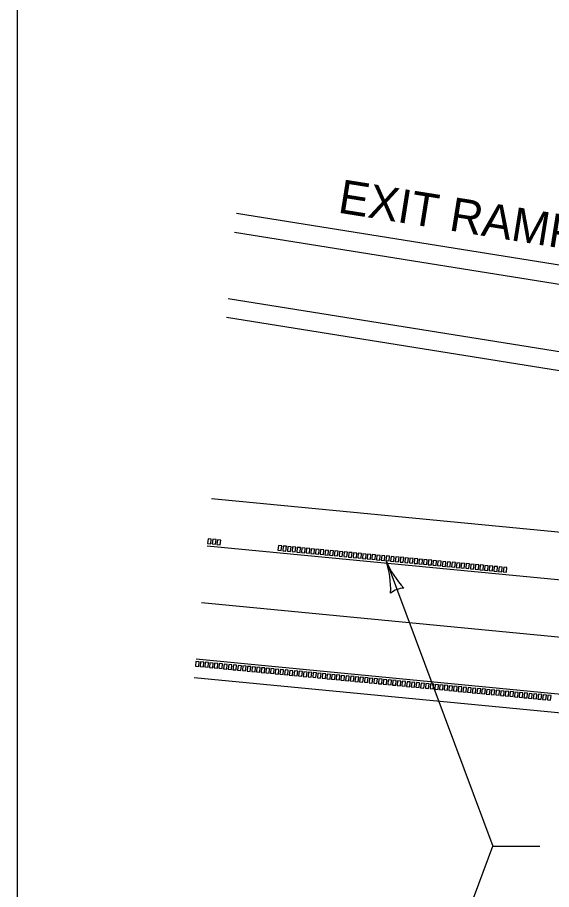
# Model space of a CAD drawing. Extents: x 49991.4 to 50021, y 49987.6 to 50011.4.
# Drawn here: x 49999.384 to 50000.652, y 49990.3 to 49992.373 of the extents above; entities that cross this region are included whole.
import ezdxf

# ---------------------------------------------------------------- set-up
doc = ezdxf.new("R2010")
doc.units = 0
for name, color, linetype in [('Level 1', 7, 'Continuous'), ('Level 2', 7, 'Continuous'), ('Level 3', 7, 'Continuous')]:
    doc.layers.add(name, color=color, linetype=linetype)

msp = doc.modelspace()

# ---------------------------------------------------------------- linework, layer by layer
at = {"layer": 'Level 1'}
for p, q in [((50003.1457, 49991.3876), (49999.9039, 49991.9068)), ((49999.8995, 49991.862), (50003.1403, 49991.3428)), ((49999.8843, 49991.7048), (50003.1155, 49991.1873)), ((50000.9907, 49991.1182), (49999.8446, 49991.2286)), ((49999.8339, 49991.1166), (50000.9799, 49991.0062)), ((49999.8209, 49990.9822), (50000.967, 49990.8718)), ((49999.8079, 49990.8478), (50000.9541, 49990.7374)), ((50000.9497, 49990.6926), (49999.8035, 49990.803))]:
    msp.add_line(p, q, dxfattribs=at)
for points in [[(49999.3835, 49998.9992), (50016.7501, 49998.9992), (50016.7501, 49987.7988), (49999.3835, 49987.7988)], [(49999.8353, 49991.1223), (49999.8431, 49991.1215), (49999.8441, 49991.1327), (49999.8364, 49991.1334)], [(49999.8465, 49991.1212), (49999.8542, 49991.1205), (49999.8553, 49991.1316), (49999.8475, 49991.1324)], [(49999.8576, 49991.1201), (49999.8654, 49991.1194), (49999.8664, 49991.1305), (49999.8587, 49991.1313)], [(50000.0025, 49991.1062), (50000.0103, 49991.1054), (50000.0114, 49991.1166), (50000.0036, 49991.1173)], [(50000.0137, 49991.1051), (50000.0214, 49991.1043), (50000.0225, 49991.1155), (50000.0148, 49991.1162)], [(50000.0248, 49991.104), (50000.0326, 49991.1033), (50000.0337, 49991.1144), (50000.0259, 49991.1152)], [(50000.036, 49991.1029), (50000.0437, 49991.1022), (50000.0448, 49991.1133), (50000.037, 49991.1141)], [(50000.0471, 49991.1019), (50000.0549, 49991.1011), (50000.056, 49991.1123), (50000.0482, 49991.113)], [(50000.0583, 49991.1008), (50000.066, 49991.1001), (50000.0671, 49991.1112), (50000.0593, 49991.1119)], [(50000.0694, 49991.0997), (50000.0772, 49991.099), (50000.0783, 49991.1101), (50000.0705, 49991.1109)], [(50000.0806, 49991.0987), (50000.0883, 49991.0979), (50000.0894, 49991.1091), (50000.0816, 49991.1098)], [(50000.0917, 49991.0976), (50000.0995, 49991.0968), (50000.1006, 49991.108), (50000.0928, 49991.1087)], [(50000.1029, 49991.0965), (50000.1106, 49991.0958), (50000.1117, 49991.1069), (50000.1039, 49991.1077)], [(50000.114, 49991.0954), (50000.1218, 49991.0947), (50000.1229, 49991.1058), (50000.1151, 49991.1066)], [(50000.1252, 49991.0944), (50000.1329, 49991.0936), (50000.134, 49991.1048), (50000.1262, 49991.1055)], [(50000.1363, 49991.0933), (50000.1441, 49991.0925), (50000.1451, 49991.1037), (50000.1374, 49991.1044)], [(50000.1475, 49991.0922), (50000.1552, 49991.0915), (50000.1563, 49991.1026), (50000.1485, 49991.1034)], [(50000.1586, 49991.0911), (50000.1664, 49991.0904), (50000.1674, 49991.1015), (50000.1597, 49991.1023)], [(50000.1698, 49991.0901), (50000.1775, 49991.0893), (50000.1786, 49991.1005), (50000.1708, 49991.1012)], [(50000.1809, 49991.089), (50000.1887, 49991.0882), (50000.1897, 49991.0994), (50000.182, 49991.1001)], [(50000.1921, 49991.0879), (50000.1998, 49991.0872), (50000.2009, 49991.0983), (50000.1931, 49991.0991)], [(50000.2032, 49991.0868), (50000.211, 49991.0861), (50000.212, 49991.0972), (50000.2043, 49991.098)], [(50000.2143, 49991.0858), (50000.2221, 49991.085), (50000.2232, 49991.0962), (50000.2154, 49991.0969)], [(50000.2255, 49991.0847), (50000.2333, 49991.0839), (50000.2343, 49991.0951), (50000.2266, 49991.0958)], [(50000.2366, 49991.0836), (50000.2444, 49991.0829), (50000.2455, 49991.094), (50000.2377, 49991.0948)], [(50000.2478, 49991.0825), (50000.2556, 49991.0818), (50000.2566, 49991.0929), (50000.2489, 49991.0937)], [(50000.2589, 49991.0815), (50000.2667, 49991.0807), (50000.2678, 49991.0919), (50000.26, 49991.0926)], [(50000.2701, 49991.0804), (50000.2779, 49991.0796), (50000.2789, 49991.0908), (50000.2712, 49991.0915)], [(50000.2812, 49991.0793), (50000.289, 49991.0786), (50000.2901, 49991.0897), (50000.2823, 49991.0905)], [(50000.2924, 49991.0782), (50000.3002, 49991.0775), (50000.3012, 49991.0886), (50000.2935, 49991.0894)], [(50000.3035, 49991.0772), (50000.3113, 49991.0764), (50000.3124, 49991.0876), (50000.3046, 49991.0883)], [(50000.3147, 49991.0761), (50000.3224, 49991.0754), (50000.3235, 49991.0865), (50000.3158, 49991.0872)], [(50000.3258, 49991.075), (50000.3336, 49991.0743), (50000.3347, 49991.0854), (50000.3269, 49991.0862)], [(50000.337, 49991.074), (50000.3447, 49991.0732), (50000.3458, 49991.0844), (50000.3381, 49991.0851)], [(50000.3481, 49991.0729), (50000.3559, 49991.0721), (50000.357, 49991.0833), (50000.3492, 49991.084)], [(50000.3593, 49991.0718), (50000.367, 49991.0711), (50000.3681, 49991.0822), (50000.3604, 49991.083)], [(50000.3704, 49991.0707), (50000.3782, 49991.07), (50000.3793, 49991.0811), (50000.3715, 49991.0819)], [(50000.3816, 49991.0697), (50000.3893, 49991.0689), (50000.3904, 49991.0801), (50000.3826, 49991.0808)], [(50000.3927, 49991.0686), (50000.4005, 49991.0678), (50000.4016, 49991.079), (50000.3938, 49991.0797)], [(50000.4039, 49991.0675), (50000.4116, 49991.0668), (50000.4127, 49991.0779), (50000.4049, 49991.0787)], [(50000.415, 49991.0664), (50000.4228, 49991.0657), (50000.4239, 49991.0768), (50000.4161, 49991.0776)], [(50000.4262, 49991.0654), (50000.4339, 49991.0646), (50000.435, 49991.0758), (50000.4272, 49991.0765)], [(50000.4373, 49991.0643), (50000.4451, 49991.0635), (50000.4462, 49991.0747), (50000.4384, 49991.0754)], [(50000.4485, 49991.0632), (50000.4562, 49991.0625), (50000.4573, 49991.0736), (50000.4495, 49991.0744)], [(50000.4596, 49991.0621), (50000.4674, 49991.0614), (50000.4685, 49991.0725), (50000.4607, 49991.0733)], [(50000.4708, 49991.0611), (50000.4785, 49991.0603), (50000.4796, 49991.0715), (50000.4718, 49991.0722)], [(50000.4819, 49991.06), (50000.4897, 49991.0592), (50000.4907, 49991.0704), (50000.483, 49991.0711)], [(50000.4931, 49991.0589), (50000.5008, 49991.0582), (50000.5019, 49991.0693), (50000.4941, 49991.0701)], [(50000.5042, 49991.0578), (50000.512, 49991.0571), (50000.513, 49991.0682), (50000.5053, 49991.069)], [(50000.5154, 49991.0568), (50000.5231, 49991.056), (50000.5242, 49991.0672), (50000.5164, 49991.0679)], [(50000.5265, 49991.0557), (50000.5343, 49991.0549), (50000.5353, 49991.0661), (50000.5276, 49991.0668)], [(50000.5377, 49991.0546), (50000.5454, 49991.0539), (50000.5465, 49991.065), (50000.5387, 49991.0658)], [(49999.8063, 49990.8309), (49999.8141, 49990.8302), (49999.8152, 49990.8413), (49999.8074, 49990.8421)], [(49999.8175, 49990.8298), (49999.8252, 49990.8291), (49999.8263, 49990.8402), (49999.8185, 49990.841)], [(49999.8286, 49990.8288), (49999.8364, 49990.828), (49999.8375, 49990.8392), (49999.8297, 49990.8399)], [(49999.8398, 49990.8277), (49999.8475, 49990.8269), (49999.8486, 49990.8381), (49999.8408, 49990.8388)], [(49999.8509, 49990.8266), (49999.8587, 49990.8259), (49999.8598, 49990.837), (49999.852, 49990.8378)], [(49999.8621, 49990.8255), (49999.8698, 49990.8248), (49999.8709, 49990.8359), (49999.8631, 49990.8367)], [(49999.8732, 49990.8245), (49999.881, 49990.8237), (49999.8821, 49990.8349), (49999.8743, 49990.8356)], [(49999.8844, 49990.8234), (49999.8921, 49990.8226), (49999.8932, 49990.8338), (49999.8854, 49990.8345)], [(49999.8955, 49990.8223), (49999.9033, 49990.8216), (49999.9043, 49990.8327), (49999.8966, 49990.8335)], [(49999.9067, 49990.8212), (49999.9144, 49990.8205), (49999.9155, 49990.8316), (49999.9077, 49990.8324)], [(49999.9178, 49990.8202), (49999.9256, 49990.8194), (49999.9266, 49990.8306), (49999.9189, 49990.8313)], [(49999.929, 49990.8191), (49999.9367, 49990.8183), (49999.9378, 49990.8295), (49999.93, 49990.8302)], [(49999.9401, 49990.818), (49999.9479, 49990.8173), (49999.9489, 49990.8284), (49999.9412, 49990.8292)], [(49999.9513, 49990.8169), (49999.959, 49990.8162), (49999.9601, 49990.8273), (49999.9523, 49990.8281)], [(49999.9624, 49990.8159), (49999.9702, 49990.8151), (49999.9712, 49990.8263), (49999.9635, 49990.827)], [(49999.9735, 49990.8148), (49999.9813, 49990.814), (49999.9824, 49990.8252), (49999.9746, 49990.8259)], [(49999.9847, 49990.8137), (49999.9925, 49990.813), (49999.9935, 49990.8241), (49999.9858, 49990.8249)], [(49999.9958, 49990.8126), (50000.0036, 49990.8119), (50000.0047, 49990.823), (49999.9969, 49990.8238)], [(50000.007, 49990.8116), (50000.0148, 49990.8108), (50000.0158, 49990.822), (50000.0081, 49990.8227)], [(50000.0181, 49990.8105), (50000.0259, 49990.8098), (50000.027, 49990.8209), (50000.0192, 49990.8216)], [(50000.0293, 49990.8094), (50000.0371, 49990.8087), (50000.0381, 49990.8198), (50000.0304, 49990.8206)], [(50000.0404, 49990.8084), (50000.0482, 49990.8076), (50000.0493, 49990.8188), (50000.0415, 49990.8195)], [(50000.0516, 49990.8073), (50000.0594, 49990.8065), (50000.0604, 49990.8177), (50000.0527, 49990.8184)], [(50000.0627, 49990.8062), (50000.0705, 49990.8055), (50000.0716, 49990.8166), (50000.0638, 49990.8174)], [(50000.0739, 49990.8051), (50000.0816, 49990.8044), (50000.0827, 49990.8155), (50000.075, 49990.8163)], [(50000.085, 49990.8041), (50000.0928, 49990.8033), (50000.0939, 49990.8145), (50000.0861, 49990.8152)], [(50000.0962, 49990.803), (50000.1039, 49990.8022), (50000.105, 49990.8134), (50000.0973, 49990.8141)], [(50000.1073, 49990.8019), (50000.1151, 49990.8012), (50000.1162, 49990.8123), (50000.1084, 49990.8131)], [(50000.1185, 49990.8008), (50000.1262, 49990.8001), (50000.1273, 49990.8112), (50000.1196, 49990.812)], [(50000.1296, 49990.7998), (50000.1374, 49990.799), (50000.1385, 49990.8102), (50000.1307, 49990.8109)], [(50000.1408, 49990.7987), (50000.1485, 49990.7979), (50000.1496, 49990.8091), (50000.1418, 49990.8098)], [(50000.1519, 49990.7976), (50000.1597, 49990.7969), (50000.1608, 49990.808), (50000.153, 49990.8088)], [(50000.1631, 49990.7965), (50000.1708, 49990.7958), (50000.1719, 49990.8069), (50000.1641, 49990.8077)], [(50000.1742, 49990.7955), (50000.182, 49990.7947), (50000.1831, 49990.8059), (50000.1753, 49990.8066)], [(50000.1854, 49990.7944), (50000.1931, 49990.7936), (50000.1942, 49990.8048), (50000.1864, 49990.8055)], [(50000.1965, 49990.7933), (50000.2043, 49990.7926), (50000.2054, 49990.8037), (50000.1976, 49990.8045)], [(50000.2077, 49990.7922), (50000.2154, 49990.7915), (50000.2165, 49990.8026), (50000.2087, 49990.8034)], [(50000.2188, 49990.7912), (50000.2266, 49990.7904), (50000.2277, 49990.8016), (50000.2199, 49990.8023)], [(50000.23, 49990.7901), (50000.2377, 49990.7894), (50000.2388, 49990.8005), (50000.231, 49990.8012)], [(50000.2411, 49990.789), (50000.2489, 49990.7883), (50000.2499, 49990.7994), (50000.2422, 49990.8002)], [(50000.2523, 49990.788), (50000.26, 49990.7872), (50000.2611, 49990.7984), (50000.2533, 49990.7991)], [(50000.2634, 49990.7869), (50000.2712, 49990.7861), (50000.2722, 49990.7973), (50000.2645, 49990.798)], [(50000.2746, 49990.7858), (50000.2823, 49990.7851), (50000.2834, 49990.7962), (50000.2756, 49990.797)], [(50000.2857, 49990.7847), (50000.2935, 49990.784), (50000.2945, 49990.7951), (50000.2868, 49990.7959)], [(50000.2969, 49990.7837), (50000.3046, 49990.7829), (50000.3057, 49990.7941), (50000.2979, 49990.7948)], [(50000.308, 49990.7826), (50000.3158, 49990.7818), (50000.3168, 49990.793), (50000.3091, 49990.7937)], [(50000.3191, 49990.7815), (50000.3269, 49990.7808), (50000.328, 49990.7919), (50000.3202, 49990.7927)], [(50000.3303, 49990.7804), (50000.3381, 49990.7797), (50000.3391, 49990.7908), (50000.3314, 49990.7916)], [(50000.3414, 49990.7794), (50000.3492, 49990.7786), (50000.3503, 49990.7898), (50000.3425, 49990.7905)], [(50000.3526, 49990.7783), (50000.3604, 49990.7775), (50000.3614, 49990.7887), (50000.3537, 49990.7894)], [(50000.3637, 49990.7772), (50000.3715, 49990.7765), (50000.3726, 49990.7876), (50000.3648, 49990.7884)], [(50000.3749, 49990.7761), (50000.3827, 49990.7754), (50000.3837, 49990.7865), (50000.376, 49990.7873)], [(50000.386, 49990.7751), (50000.3938, 49990.7743), (50000.3949, 49990.7855), (50000.3871, 49990.7862)], [(50000.3972, 49990.774), (50000.405, 49990.7732), (50000.406, 49990.7844), (50000.3983, 49990.7851)], [(50000.4083, 49990.7729), (50000.4161, 49990.7722), (50000.4172, 49990.7833), (50000.4094, 49990.7841)], [(50000.4195, 49990.7718), (50000.4272, 49990.7711), (50000.4283, 49990.7822), (50000.4206, 49990.783)], [(50000.4306, 49990.7708), (50000.4384, 49990.77), (50000.4395, 49990.7812), (50000.4317, 49990.7819)], [(50000.4418, 49990.7697), (50000.4495, 49990.7689), (50000.4506, 49990.7801), (50000.4429, 49990.7808)], [(50000.4529, 49990.7686), (50000.4607, 49990.7679), (50000.4618, 49990.779), (50000.454, 49990.7798)], [(50000.4641, 49990.7675), (50000.4718, 49990.7668), (50000.4729, 49990.7779), (50000.4652, 49990.7787)], [(50000.4752, 49990.7665), (50000.483, 49990.7657), (50000.4841, 49990.7769), (50000.4763, 49990.7776)], [(50000.4864, 49990.7654), (50000.4941, 49990.7647), (50000.4952, 49990.7758), (50000.4874, 49990.7765)], [(50000.4975, 49990.7643), (50000.5053, 49990.7636), (50000.5064, 49990.7747), (50000.4986, 49990.7755)], [(50000.5087, 49990.7633), (50000.5164, 49990.7625), (50000.5175, 49990.7737), (50000.5097, 49990.7744)], [(50000.5198, 49990.7622), (50000.5276, 49990.7614), (50000.5287, 49990.7726), (50000.5209, 49990.7733)], [(50000.531, 49990.7611), (50000.5387, 49990.7604), (50000.5398, 49990.7715), (50000.532, 49990.7723)], [(50000.5421, 49990.76), (50000.5499, 49990.7593), (50000.551, 49990.7704), (50000.5432, 49990.7712)], [(50000.5533, 49990.759), (50000.561, 49990.7582), (50000.5621, 49990.7694), (50000.5543, 49990.7701)], [(50000.5644, 49990.7579), (50000.5722, 49990.7571), (50000.5733, 49990.7683), (50000.5655, 49990.769)], [(50000.5756, 49990.7568), (50000.5833, 49990.7561), (50000.5844, 49990.7672), (50000.5766, 49990.768)], [(50000.5867, 49990.7557), (50000.5945, 49990.755), (50000.5955, 49990.7661), (50000.5878, 49990.7669)], [(50000.5979, 49990.7547), (50000.6056, 49990.7539), (50000.6067, 49990.7651), (50000.5989, 49990.7658)], [(50000.609, 49990.7536), (50000.6168, 49990.7528), (50000.6178, 49990.764), (50000.6101, 49990.7647)], [(50000.6202, 49990.7525), (50000.6279, 49990.7518), (50000.629, 49990.7629), (50000.6212, 49990.7637)], [(50000.6313, 49990.7514), (50000.6391, 49990.7507), (50000.6401, 49990.7618), (50000.6324, 49990.7626)], [(50000.6425, 49990.7504), (50000.6502, 49990.7496), (50000.6513, 49990.7608), (50000.6435, 49990.7615)]]:
    msp.add_lwpolyline(points, close=True, dxfattribs=at)
msp.add_lwpolyline([(49999.8801, 49991.66), (50004.6375, 49990.8979)], dxfattribs=at)
at = {"layer": 'Level 3'}
for p, q in [((50000.2593, 49991.0814), (50000.5133, 49990.4024)), ((50000.318, 49989.8802), (50000.5133, 49990.4024)), ((50000.5133, 49990.4024), (50000.6247, 49990.4024))]:
    msp.add_line(p, q, dxfattribs=at)
for centre, radius, start, end in [((50000.048, 49991.0122), 0.2223, 357.9677, 18.1512), ((50000.4732, 49991.1737), 0.233, 203.339, 222.5889), ((50000.3042, 49990.9613), 0.0548, 92.6505, 128.3729)]:
    msp.add_arc(centre, radius, start, end, dxfattribs=at)

# ---------------------------------------------------------------- texts
at = {"layer": 'Level 2'}
msp.add_text('EXIT RAMP', height=0.08, rotation=350.9, dxfattribs=at).set_placement((50000.1426, 49991.9091))

doc.saveas('drawing.dxf')
